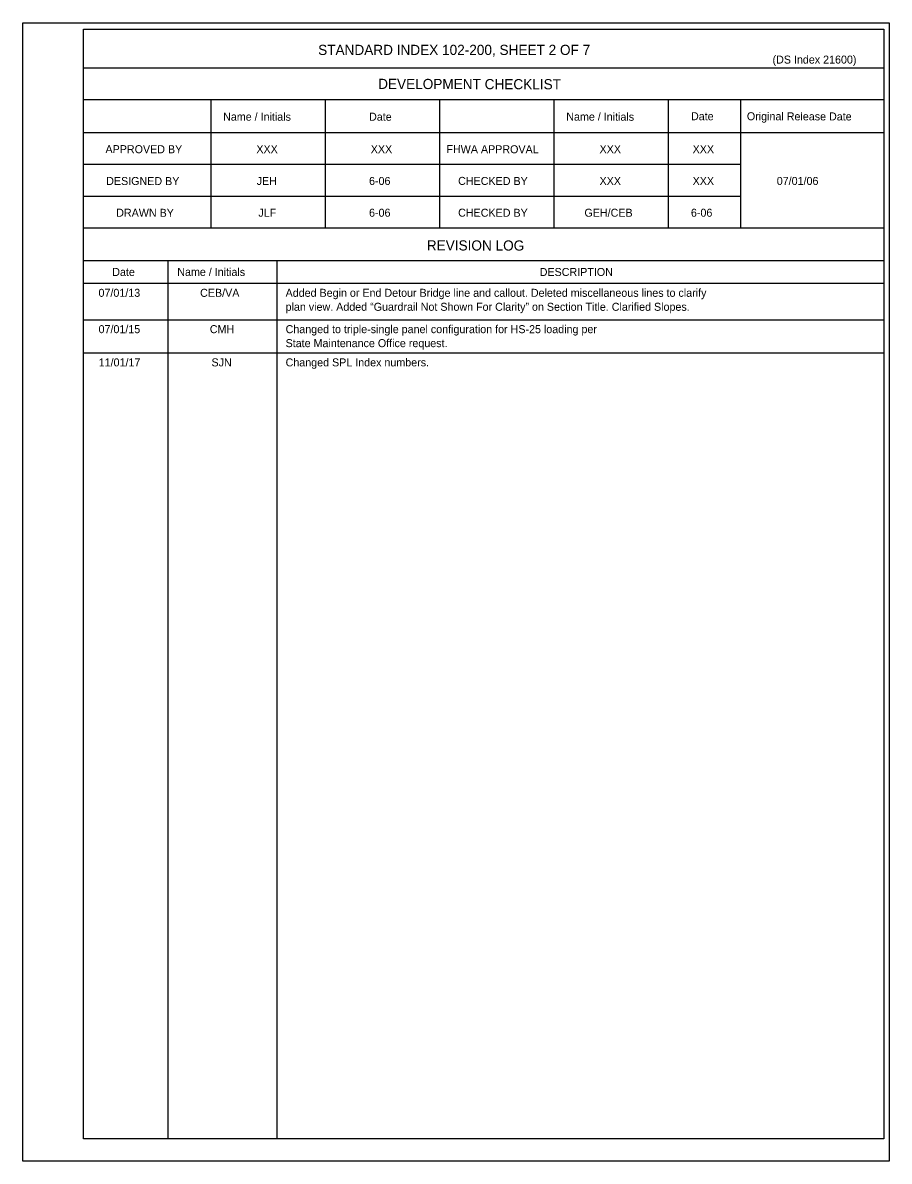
# Model space of a CAD drawing. Extents: x 10618 to 10724, y 76431 to 76484.
# Drawn here: x 10691.48 to 10724.2, y 76441.32 to 76484.32 of the extents above; entities that cross this region are included whole.
import ezdxf

# ---------------------------------------------------------------- set-up
doc = ezdxf.new("R2010")
doc.units = 0
for name, color, linetype in [('Border', 7, 'Continuous'), ('PlotBorder_dp', 7, 'Continuous'), ('TextStructures', 7, 'Continuous')]:
    doc.layers.add(name, color=color, linetype=linetype)

msp = doc.modelspace()

# ---------------------------------------------------------------- linework, layer by layer
at = {"layer": 'Border'}
for p, q in [((10723.992, 76482.607), (10693.772, 76482.607)), ((10723.992, 76481.407), (10693.772, 76481.407)), ((10698.572, 76481.407), (10698.572, 76476.565)), ((10702.892, 76481.407), (10702.892, 76476.565)), ((10707.212, 76481.407), (10707.212, 76476.565)), ((10711.532, 76481.407), (10711.532, 76476.565)), ((10715.852, 76481.407), (10715.852, 76476.565)), ((10718.574, 76481.407), (10718.574, 76476.565)), ((10723.992, 76480.165), (10693.772, 76480.165)), ((10718.574, 76478.965), (10693.772, 76478.965)), ((10718.574, 76477.765), (10693.772, 76477.765)), ((10723.992, 76476.565), (10693.772, 76476.565)), ((10723.992, 76475.324), (10693.772, 76475.324)), ((10696.952, 76475.324), (10696.952, 76442.164)), ((10701.066, 76475.324), (10701.066, 76442.164)), ((10723.992, 76474.478), (10693.772, 76474.478))]:
    msp.add_line(p, q, dxfattribs=at)
msp.add_lwpolyline([(10693.772, 76484.078), (10723.992, 76484.078), (10723.992, 76442.164), (10693.772, 76442.164)], close=True, dxfattribs=at)
at = {"layer": 'PlotBorder_dp'}
msp.add_line((10691.476, 76441.322), (10691.476, 76441.322), dxfattribs=at)
msp.add_lwpolyline([(10691.476, 76484.322), (10724.196, 76484.322), (10724.196, 76441.322), (10691.476, 76441.322)], close=True, dxfattribs=at)
at = {"layer": 'TextStructures'}
for p, q in [((10693.772, 76473.105), (10723.992, 76473.105)), ((10693.772, 76471.85), (10723.992, 76471.85))]:
    msp.add_line(p, q, dxfattribs=at)

# ---------------------------------------------------------------- texts
for s, height, p in [('STANDARD INDEX 102-200, SHEET 2 OF 7', 0.384, (10702.63, 76483.106)), ('(DS Index 21600)', 0.3024, (10719.789, 76482.78)), ('XXX', 0.3024, (10700.297, 76479.396)), ('XXX', 0.3024, (10704.617, 76479.396)), ('XXX', 0.3024, (10713.257, 76479.396)), ('XXX', 0.3024, (10716.772, 76479.396)), ('JEH', 0.3024, (10700.308, 76478.196)), ('6-06', 0.3024, (10704.552, 76478.196)), ('XXX', 0.3024, (10713.257, 76478.196)), ('XXX', 0.3024, (10716.772, 76478.196)), ('07/01/06', 0.3024, (10719.949, 76478.196)), ('JLF', 0.3024, (10700.371, 76476.996)), ('6-06', 0.3024, (10704.552, 76476.996)), ('GEH/CEB', 0.3024, (10712.686, 76476.996)), ('6-06', 0.3024, (10716.707, 76476.996)), ('DESCRIPTION', 0.3024, (10710.997, 76474.758)), ('07/01/13', 0.3024, (10694.336, 76473.971)), ('CEB/VA', 0.3024, (10698.173, 76473.971)), ('Added Begin or End Detour Bridge line and callout. Deleted miscellaneous lines to clarify', 0.3024, (10701.401, 76473.971)), ('plan view. Added “Guardrail Not Shown For Clarity” on Section Title. Clarified Slopes.', 0.3024, (10701.401, 76473.443)), ('07/01/15', 0.3024, (10694.338, 76472.598)), ('CMH', 0.3024, (10698.539, 76472.598)), ('Changed to triple-single panel configuration for HS-25 loading per', 0.3024, (10701.401, 76472.598)), ('State Maintenance Office request.', 0.3024, (10701.401, 76472.07)), ('11/01/17', 0.3024, (10694.343, 76471.343)), ('SJN', 0.3024, (10698.603, 76471.343)), ('Changed SPL Index numbers.', 0.3024, (10701.401, 76471.343))]:
    msp.add_text(s, height=height, dxfattribs=at).set_placement(p)
for s, height, p in [('DEVELOPMENT CHECKLIST', 0.384, (10704.895, 76481.822)), ('Name / Initials', 0.3024, (10699.041, 76480.626)), ('Name / Initials', 0.3024, (10712, 76480.626)), ('Date', 0.3024, (10716.71, 76480.641)), ('Original Release Date', 0.3024, (10718.82, 76480.64)), ('Date', 0.3024, (10704.552, 76480.623)), ('APPROVED BY', 0.3024, (10694.599, 76479.398)), ('FHWA APPROVAL', 0.3024, (10707.474, 76479.398)), ('DESIGNED BY', 0.3024, (10694.625, 76478.196)), ('CHECKED BY', 0.3024, (10707.916, 76478.198)), ('DRAWN BY', 0.3024, (10695.004, 76476.996)), ('CHECKED BY', 0.3024, (10707.916, 76476.998)), ('REVISION LOG', 0.384, (10706.733, 76475.724)), ('Date', 0.3024, (10694.855, 76474.759)), ('Name / Initials', 0.3024, (10697.31, 76474.762))]:
    msp.add_text(s, height=height, rotation=359.8756, dxfattribs=at).set_placement(p)

doc.saveas('drawing.dxf')
